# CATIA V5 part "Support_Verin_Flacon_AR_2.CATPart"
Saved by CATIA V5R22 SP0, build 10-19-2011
Part number: Support_Verin_Flacon_AR_2
Bounding box of the stored display mesh (mm): x 0 to 9, y -28.5 to 28.5, z -20 to 18.312
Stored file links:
  U:\S9A\PER\CAO\Assemblage\Reservoir_Flacon\Verin\Poussoir_2\Support_Verin_Flacon_AR_2.CATPart
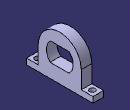
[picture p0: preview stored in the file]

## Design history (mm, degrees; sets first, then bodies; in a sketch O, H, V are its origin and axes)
Body1 (main body)
  Sketch1 on yz-plane, origin (0, 0, 0), H (0, 1, 0), V (0, 0, 1)
    arc A1 centre (0, 0) radius 11.5 from (8.2614, -8) to (8.2614, 8) ccw
    point P1 (-8.2614, 8)
    line L1 (-8.2614, 8) -> (8.2614, 8)
    line L2 (8.2614, -8) -> (-8.2614, -8)
    arc A2 centre (0, 0) radius 11.5 from (-8.2614, 8) to (-8.2614, -8) ccw
    arc A3 centre (0, 0) radius 18.5 from (18.5, 0) to (-18.5, 0) ccw
    point P5 (18.5, -20)
    line L3 (18.5, -20) -> (-18.5, -20)
    line L4 (-18.5, -15) -> (-18.5, 0)
    line L5 (18.5, 0) -> (18.5, -15)
    point P6 (-18.5, -20)
    point P7 (-18.5, 0)
    line L6 (-18.5, -20) -> (-28.5, -20)
    line L7 (-28.5, -20) -> (-28.5, -15)
    line L8 (-28.5, -15) -> (-18.5, -15)
    point P9 (-28.5, -20)
    point P10 (-28.5, -15)
    point P11 (-18.5, -15)
    point P12 (18.5, -20)
    point P13 (28.5, -20)
    point P14 (28.5, -15)
    point P15 (18.5, -15)
    line L9 (18.5, -20) -> (28.5, -20)
    line L10 (28.5, -20) -> (28.5, -15)
    line L11 (28.5, -15) -> (18.5, -15)
    radius A1 = 11.5
    distance O L2 = 8
    distance A3 A1 = 7
    distance H L3 = 20
    length L7 = 5
    length L8 = 10
    horizontal: L1 H, L2 H, L3 H, L6 H, L8 H
    equidistance: L2 L1 O
    coincidence: P1 A1, A1 A2, P7 H, P6 L4, P5 L5, P5 P12
    vertical: L4 V, L5 V, L7 V
    tangency: L5 A3
    symmetry: P6 P12 V, P9 P13 V, P10 P14 V, P11 P15 V, L6 L9 V, L7 L10 V, L8 L11 V
  Pad1: profile Sketch1, direction (1, 0, 0), length 9
  Sketch2 on face of Pad1 from Sketch1.L8, origin (4.0945, -21.7064, -15), H (1, 0, 0), V (0, 1, 0)
    point P1 (0.4055, -1.7936)
    reference projected point E1 (-4.0945, -6.7936) from vertex [face of Pad1 from Sketch1.L7 | start face of Pad1 | face of Pad1 from Sketch1.L8]
    reference projected point E2 (4.9055, 3.2064) from vertex [face of Pad1 from Sketch1.L4 | end face of Pad1 | face of Pad1 from Sketch1.A3]
    reference projected point E3 (4.9055, -6.7936) from vertex [face of Pad1 from Sketch1.L7 | end face of Pad1 | face of Pad1 from Sketch1.L8]
    reference projected point E4 (-4.0945, 3.2064) from vertex [face of Pad1 from Sketch1.L4 | start face of Pad1 | face of Pad1 from Sketch1.A3]
    equidistance: E1 E2 P1, E3 E4 P1
  Hole1: placed by Sketch2, at (4.5, -23.5, -15) direction (0, 0, -1), diameter 5, through (limit type 6)
  Mirror1: of Hole1, about zx-plane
